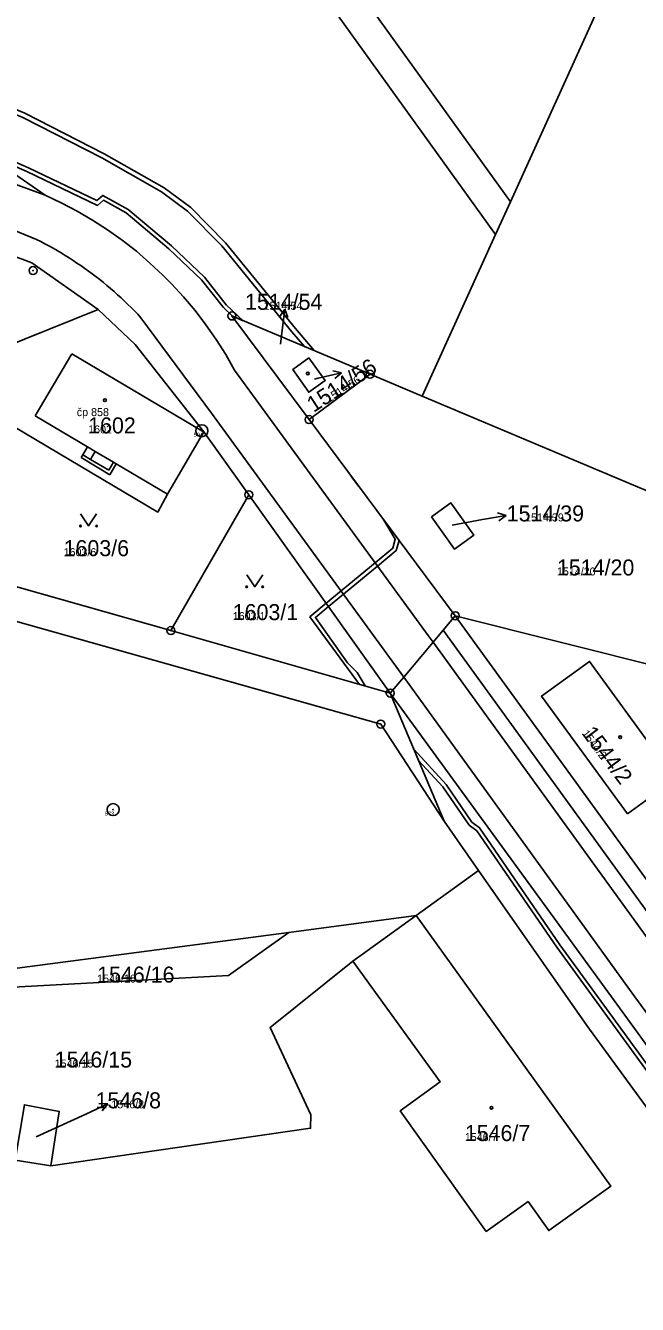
# Model space of a CAD drawing. Extents: x -763628 to -761565, y -976033 to -973833.
# Drawn here: x -763120.4 to -763043.9, y -975492.5 to -975332.7 of the extents above; entities that cross this region are included whole.
import ezdxf

# ---------------------------------------------------------------- set-up
doc = ezdxf.new("R2010")
doc.units = 0
for name, color, linetype in [('KN_cisla parcel 1000', 7, 'Continuous'), ('KN_cisla parcel 500', 7, 'Continuous'), ('KN_cisla parcel znacky', 7, 'Continuous'), ('KN_cisla popisna 500', 7, 'Continuous'), ('KN_hranice parcel', 7, 'Continuous'), ('KN_vecna bremena', 7, 'Continuous'), ('KN_vnitrni kresba parcel', 7, 'Continuous'), ('KN_znacky bodu BP', 7, 'Continuous'), ('KN_znacky budov', 7, 'Continuous'), ('KN_znacky kultur', 7, 'Continuous')]:
    doc.layers.add(name, color=color, linetype=linetype)

msp = doc.modelspace()

# ---------------------------------------------------------------- linework, layer by layer
at = {"layer": 'KN_cisla parcel znacky'}
for p, q in [((-763087.98, -975368.14), (-763088.6, -975369.07)), ((-763088.35, -975371.12), (-763087.98, -975368.14)), ((-763087.98, -975368.14), (-763087.61, -975369.2)), ((-763088.52, -975372.52), (-763088.35, -975371.12)), ((-763084.27, -975376.9), (-763083.82, -975376.79)), ((-763083.82, -975376.79), (-763080.9, -975376.11)), ((-763080.9, -975376.11), (-763081.98, -975375.85)), ((-763080.9, -975376.11), (-763081.76, -975376.83)), ((-763067.08, -975395.13), (-763063.31, -975394.44)), ((-763063.31, -975394.44), (-763060.35, -975393.92)), ((-763060.35, -975393.92), (-763061.43, -975393.6)), ((-763060.35, -975393.92), (-763061.25, -975394.59)), ((-763112.84, -975468.72), (-763110.12, -975467.45)), ((-763110.12, -975467.45), (-763111.24, -975467.42)), ((-763110.12, -975467.45), (-763110.82, -975468.33)), ((-763119.07, -975471.56), (-763112.84, -975468.72))]:
    msp.add_line(p, q, dxfattribs=at)
at = {"layer": 'KN_hranice parcel'}
for p, q in [((-763061.66, -975358.82), (-763119.04, -975279.09)), ((-763111.94, -975282.33), (-763059.81, -975354.74)), ((-763059.81, -975354.74), (-763061.66, -975358.82)), ((-763070.81, -975379.03), (-763061.66, -975358.82)), ((-763123.5, -975373.12), (-763111.31, -975368.2)), ((-763084.95, -975381.96), (-763077.34, -975376.28)), ((-763077.34, -975376.28), (-763070.81, -975379.03)), ((-763066.69, -975406.46), (-763084.95, -975381.96)), ((-763098.11, -975383.49), (-763092.5, -975391.34)), ((-763092.5, -975391.34), (-763102.23, -975408.32)), ((-763092.5, -975391.34), (-763074.81, -975416.13)), ((-763102.23, -975408.32), (-763124.87, -975401.88)), ((-763018.61, -975418.55), (-763066.69, -975406.46)), ((-763066.69, -975406.46), (-763036.65, -975447.94)), ((-763102.23, -975408.32), (-763074.81, -975416.13)), ((-763074.81, -975416.13), (-763068.1, -975432.11)), ((-763063.78, -975438.29), (-763068.1, -975432.11)), ((-763071.58, -975443.92), (-763063.78, -975438.29)), ((-763087.5, -975446.02), (-763071.58, -975443.92)), ((-763071.58, -975443.92), (-763079.49, -975449.63)), ((-763121.68, -975474.47), (-763117.24, -975475.18))]:
    msp.add_line(p, q, dxfattribs=at)
for points in [[(-763059.81, -975354.74), (-763043.52, -975318.79), (-762991.97, -975333.73), (-762984.8, -975335.08)], [(-763117.94, -975353.91), (-763125.03, -975349.04), (-763163.61, -975331.77), (-763210.7, -975321.11)], [(-763094.26, -975375.78), (-763095.37, -975373.84), (-763096.57, -975371.95), (-763097.85, -975370.11), (-763099.21, -975368.34), (-763100.65, -975366.62), (-763102.16, -975364.98), (-763103.21, -975363.92), (-763104.84, -975362.39), (-763106.54, -975360.93), (-763108.3, -975359.55), (-763110.13, -975358.25), (-763112.01, -975357.04), (-763113.94, -975355.91), (-763115.92, -975354.86), (-763117.94, -975353.91)], [(-763111.31, -975368.2), (-763119.6, -975362.37), (-763120.82, -975361.93), (-763138.61, -975355.57)], [(-763098.11, -975383.49), (-763106.69, -975372.56), (-763111.31, -975368.2)], [(-763077.34, -975376.28), (-763094.6, -975369.01), (-763084.95, -975381.96)], [(-763084.97, -975374.25), (-763082.95, -975377.08), (-763084.99, -975378.54), (-763087, -975375.7), (-763084.97, -975374.25)], [(-763069.47, -975409.77), (-763070.09, -975408.92), (-763094.26, -975375.78)], [(-763070.81, -975379.03), (-763036.81, -975393.35), (-763029.93, -975396.25)], [(-763125.87, -975380.46), (-763120.46, -975383.67), (-763103.87, -975393.52), (-763102.66, -975391.28), (-763098.11, -975383.49)], [(-763068.1, -975432.11), (-763076.01, -975420), (-763192.16, -975387.29)], [(-763069.68, -975394.12), (-763066.77, -975398.16), (-763064.36, -975396.39), (-763067.24, -975392.36), (-763069.68, -975394.12)], [(-763066.69, -975406.46), (-763068.21, -975408.27), (-763069.47, -975409.77)], [(-763069.47, -975409.77), (-763073.13, -975414.13), (-763074.81, -975416.13)], [(-763045.19, -975431.21), (-763055.9, -975416.51), (-763049.92, -975412.18), (-763039.21, -975426.88), (-763045.19, -975431.21)], [(-762985.45, -975552.19), (-762983.97, -975548.45), (-763050.24, -975457.66), (-763063.78, -975438.29)], [(-763079.49, -975449.63), (-763068.6, -975464.71), (-763073.57, -975468.33), (-763062.82, -975483.39), (-763057.6, -975479.67), (-763055.01, -975483.29), (-763047.26, -975477.75), (-763071.58, -975443.92)], [(-763129.42, -975451.54), (-763121.42, -975450.49), (-763087.5, -975446.02)], [(-763087.5, -975446.02), (-763095.01, -975451.4), (-763127.39, -975453.15), (-763129.24, -975453.34)], [(-763079.49, -975449.63), (-763089.82, -975457.89), (-763084.74, -975468.84), (-763084.78, -975470.5), (-763117.24, -975475.18)], [(-763117.24, -975475.18), (-763116.18, -975468.39), (-763120.53, -975467.56), (-763121.68, -975474.47)]]:
    msp.add_lwpolyline(points, dxfattribs=at)
at = {"layer": 'KN_vecna bremena'}
for points in [[(-763169.01, -975328.42), (-763153.84, -975333.18), (-763144.81, -975336.13), (-763128.5, -975340.99), (-763120.74, -975344.2), (-763110.85, -975349.26), (-763103.38, -975353.48), (-763100.15, -975355.93), (-763095.85, -975360.25), (-763087.1, -975370.97), (-763085.54, -975372.83), (-763084.34, -975373.33), (-763086.64, -975370.59), (-763095.41, -975359.85), (-763099.75, -975355.47), (-763103.06, -975352.98), (-763110.57, -975348.74), (-763120.48, -975343.66), (-763128.3, -975340.43), (-763144.63, -975335.55), (-763153.66, -975332.6)], [(-763130.49, -975346.46), (-763120.23, -975350.94), (-763111.39, -975355.19), (-763110.66, -975354.55), (-763107.83, -975356.12), (-763102.5, -975360.64), (-763098.39, -975364.5), (-763095.66, -975367.96), (-763094.51, -975369.05), (-763093.21, -975369.6), (-763095.3, -975367.62), (-763098.03, -975364.16), (-763102.16, -975360.26), (-763107.55, -975355.7), (-763110.72, -975353.95), (-763111.47, -975354.59), (-763120.03, -975350.48), (-763130.31, -975346)], [(-763071.87, -975423.13), (-763071.28, -975424.54), (-763068.25, -975427.86), (-763064.97, -975432.61), (-763064.01, -975433.32), (-763054.01, -975447.86), (-763038.34, -975469.41)], [(-763037.94, -975469.11), (-763053.61, -975447.58), (-763063.65, -975432.96), (-763064.61, -975432.25), (-763067.85, -975427.54), (-763071.87, -975423.13)]]:
    msp.add_lwpolyline(points, dxfattribs=at)
for points in [[(-763078.77, -975390.26), (-763079.86, -975388.79), (-763079.54, -975389.29)], [(-763073.71, -975397.05), (-763075.74, -975394.32), (-763074.19, -975396.91), (-763074.51, -975398.02), (-763076.71, -975399.84), (-763082.82, -975404.91), (-763084.85, -975406.6), (-763078.64, -975415.04), (-763077.95, -975415.24), (-763078.93, -975413.55), (-763080.15, -975412.33), (-763084.17, -975406.68), (-763082.53, -975405.32), (-763076.42, -975400.25), (-763074.07, -975398.3)]]:
    msp.add_lwpolyline(points, close=True, dxfattribs=at)
at = {"layer": 'KN_vnitrni kresba parcel'}
for p, q in [((-763153.46, -975340.95), (-763117.94, -975353.91)), ((-763119.01, -975359.44), (-763130.74, -975354.68)), ((-763105.96, -975369.23), (-763097.16, -975381.14)), ((-763119.17, -975381.49), (-763114.58, -975373.74)), ((-763114.58, -975373.74), (-763098.36, -975383.35)), ((-763119.17, -975381.49), (-763112.64, -975385.36)), ((-763073.13, -975414.13), (-763097.16, -975381.14)), ((-763098.11, -975383.49), (-763098.36, -975383.35)), ((-763113.23, -975386.36), (-763113.44, -975386.71)), ((-763113.44, -975386.71), (-763109.84, -975388.84)), ((-763112.64, -975385.36), (-763113.23, -975386.36)), ((-763112.27, -975386.94), (-763113.23, -975386.36)), ((-763111.67, -975385.94), (-763112.64, -975385.36)), ((-763112.27, -975386.94), (-763111.67, -975385.94)), ((-763109.39, -975387.29), (-763111.67, -975385.94)), ((-763109.98, -975388.29), (-763112.27, -975386.94)), ((-763109.39, -975387.29), (-763109.98, -975388.29)), ((-763109.84, -975388.84), (-763109.05, -975387.49)), ((-763109.39, -975387.29), (-763109.05, -975387.49)), ((-763102.66, -975391.28), (-763109.05, -975387.49)), ((-763068.21, -975408.27), (-763038.52, -975449.28)), ((-763040.08, -975450.39), (-763069.47, -975409.77)), ((-763072.68, -975414.75), (-763073.13, -975414.13)), ((-763044.58, -975453.61), (-763072.68, -975414.75)), ((-763074.81, -975416.13), (-763046.51, -975454.99)), ((-762978.63, -975544.55), (-763044.58, -975453.61)), ((-762980.62, -975546), (-763046.51, -975454.99))]:
    msp.add_line(p, q, dxfattribs=at)
msp.add_lwpolyline([(-763105.96, -975369.23), (-763106.36, -975368.8), (-763106.77, -975368.38), (-763107.18, -975367.97), (-763107.6, -975367.56), (-763108.02, -975367.15), (-763108.45, -975366.75), (-763108.88, -975366.36), (-763109.32, -975365.97), (-763109.76, -975365.58), (-763110.21, -975365.21), (-763110.66, -975364.83), (-763111.12, -975364.47), (-763111.58, -975364.11), (-763112.05, -975363.75), (-763112.52, -975363.4), (-763112.99, -975363.06), (-763113.47, -975362.72), (-763113.96, -975362.39), (-763114.45, -975362.07), (-763114.94, -975361.75), (-763115.43, -975361.44), (-763115.93, -975361.14), (-763116.44, -975360.84), (-763116.94, -975360.54), (-763117.46, -975360.26), (-763117.97, -975359.98), (-763118.49, -975359.71), (-763119.01, -975359.44)], dxfattribs=at)
at = {"layer": 'KN_znacky bodu BP'}
for centre, radius in [((-763119.44, -975363.33), 0.5), ((-763119.44, -975363.33), 0.0303), ((-763094.6, -975369.01), 0.5), ((-763094.6, -975369.01), 0.0303), ((-763077.34, -975376.28), 0.5), ((-763077.34, -975376.28), 0.0303), ((-763084.95, -975381.96), 0.5), ((-763084.95, -975381.96), 0.0303), ((-763098.36, -975383.35), 0.75), ((-763098.36, -975383.35), 0.03), ((-763092.5, -975391.34), 0.5), ((-763092.5, -975391.34), 0.0303), ((-763066.69, -975406.46), 0.5), ((-763066.69, -975406.46), 0.0303), ((-763102.23, -975408.32), 0.5), ((-763102.23, -975408.32), 0.0303), ((-763074.81, -975416.13), 0.5), ((-763074.81, -975416.13), 0.0303), ((-763076.01, -975420), 0.5), ((-763076.01, -975420), 0.0303), ((-763109.44, -975430.69), 0.75), ((-763109.44, -975430.69), 0.03)]:
    msp.add_circle(centre, radius, dxfattribs=at)
at = {"layer": 'KN_znacky budov'}
for centre in [(-763085.11, -975376.19), (-763110.46, -975379.53), (-763046.08, -975421.63), (-763062.17, -975467.95)]:
    msp.add_circle(centre, 0.175, dxfattribs=at)
at = {"layer": 'KN_znacky kultur'}
for points in [[(-763113.51, -975393.75), (-763112.51, -975395.25), (-763111.51, -975393.75)], [(-763092.75, -975401.35), (-763091.75, -975402.85), (-763090.75, -975401.35)]]:
    msp.add_lwpolyline(points, dxfattribs=at)
for centre in [(-763113.51, -975395.25), (-763111.51, -975395.25), (-763092.75, -975402.85), (-763090.75, -975402.85)]:
    msp.add_circle(centre, 0.1, dxfattribs=at)

# ---------------------------------------------------------------- texts
at = {"layer": 'KN_cisla parcel 1000'}
for s, p in [('1514/54', (-763092.96, -975368.24)), ('1602', (-763112.56, -975383.68)), ('1514/39', (-763060.27, -975394.68)), ('1603/6', (-763115.63, -975399.02)), ('1514/20', (-763053.99, -975401.43)), ('1603/1', (-763094.5, -975407.01)), ('1546/16', (-763111.44, -975452.3)), ('1546/15', (-763116.74, -975462.91)), ('1546/8', (-763111.64, -975468.01)), ('1546/7', (-763065.5, -975472.1))]:
    msp.add_text(s, height=2, dxfattribs=at).set_placement(p)
for s, rotation, p in [('1514/56', 33, (-763084.4, -975381.13)), ('1544/2', 307, (-763050.94, -975421.19))]:
    msp.add_text(s, height=2, rotation=rotation, dxfattribs=at).set_placement(p)
at = {"layer": 'KN_cisla parcel 500'}
for s, p in [('1514/54', (-763090.63, -975368.24)), ('1602', (-763112.56, -975383.68)), ('1514/39', (-763057.97, -975394.68)), ('1603/6', (-763115.63, -975399.02)), ('1514/20', (-763053.99, -975401.43)), ('1603/1', (-763094.5, -975407.01)), ('1546/16', (-763111.44, -975452.3)), ('1546/15', (-763116.74, -975462.91)), ('1546/8', (-763109.66, -975468.01)), ('1546/7', (-763065.5, -975472.1))]:
    msp.add_text(s, height=1, dxfattribs=at).set_placement(p)
for s, rotation, p in [('1514/56', 33, (-763082.46, -975379.87)), ('1544/2', 307, (-763050.94, -975421.19))]:
    msp.add_text(s, height=1, rotation=rotation, dxfattribs=at).set_placement(p)
at = {"layer": 'KN_cisla popisna 500'}
msp.add_text('čp 858', height=1, dxfattribs=at).set_placement((-763113.98, -975381.52))
at = {"layer": 'KN_znacky bodu BP'}
for s, p in [('504', (-763099.37, -975384.1)), ('573', (-763110.48, -975431.44))]:
    msp.add_text(s, height=0.5, dxfattribs=at).set_placement(p)

doc.saveas('drawing.dxf')
